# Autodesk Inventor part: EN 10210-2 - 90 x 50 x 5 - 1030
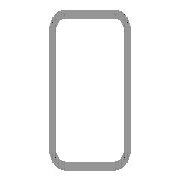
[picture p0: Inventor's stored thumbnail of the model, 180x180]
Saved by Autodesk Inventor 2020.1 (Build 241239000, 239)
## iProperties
Created: 2019-01
Part Number: EN 10210-2 - 90 x 50 x 5 - 1030
Material: Stahl, weich
Description: Rohrleitung
Document SubType Name: Modeling
Standard: DIN
Designer: lutzd
Standard Revision: 2006-07
Standards Organization: DIN
Language: de-DE
Size Designation: 90 x 50 x 5
Categories: <MemberInstance><Categories><Category DisplayName="Profile" InternalName="089c4875-fa83-4c05-b084-43b9cc11f5ed" Mnemonic="GRDR"><CategoryParameter DisplayName="
Stock Number: 90 x 50 x 5
Mass: 10294.3 g
Surface Area: 5160.42 cm^2
Volume: 1311.37 cm^3
Density: 7.85 g/cm^3
Appearance: Halbpoliert
IsCustomPart: 1
G_W: 50,000 mm
G_H: 90,000 mm
DocNumber: ADSK-014221
Folder: .
Dimensions: 50x90x1030 mm
Mass: 10,294 kg
+27136E20-D75B-4159-8830-D95EEF26A210+SCHNITTDETAIL1: Schnittwinkel 90,00 grd
+CEBB8236-4632-479D-8D11-BF2C99D5F906+SCHNITTDETAIL2: Schnittwinkel 90,00 grd
G_L: 1030,000 mm
_CCFamilyMember: 153
_CCFamilyDisplayName: DIN EN 10210-2 (USAS B17.1 rechteckig) - Rohrleitung — In Klammern angegebene Größen wurden aufgehoben
_FrameMemberDoc: Frame Member File
_Version: 15.0.0
_GetPNFromCC: 1
Title: Profil-Bauteil
Author: lutzd
Revision Number: -
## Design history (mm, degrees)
node "Startebene"
node "Endebene"
sketch "Skizze"
  geometry: L1 (-25, -37.5)-(-25, 37.5); L2 (-17.5, 45)-(17.5, 45); L3 (25, 37.5)-(25, -37.5); L4 (17.5, -45)-(-17.5, -45); L5 (-15, 40)-(15, 40); L6 (20, 35)-(20, -35); L7 (15, -40)-(-15, -40); L8 (-20, -35)-(-20, 35); L9 (0, 65.175)-(0, -65.175) reference; L10 (-37.175, 0)-(37.175, 0) reference; A1 r 7.5 centre (-17.5, -37.5) between (-25, -37.5) and (-17.5, -45); A2 r 7.5 centre (-17.5, 37.5) between (-17.5, 45) and (-25, 37.5); A3 r 7.5 centre (17.5, 37.5) between (25, 37.5) and (17.5, 45); A4 r 7.5 centre (17.5, -37.5) between (17.5, -45) and (25, -37.5); A5 r 5 centre (-15, -35) between (-20, -35) and (-15, -40); A6 r 5 centre (-15, 35) between (-15, 40) and (-20, 35); A7 r 5 centre (15, 35) between (20, 35) and (15, 40); A8 r 5 centre (15, -35) between (15, -40) and (20, -35)
  constraints: 16 end point, 16 point on circle, 16 tangent, 8 centre point, 6 equal radius, 4 parallel, 2 perpendicular, 2 other
  dimensions: "d7" = 7.5 radius of A1 (= G_IR); "d10" = 90 distance between parallel lines of L2 L4 (= G_H); "d11" = 50 distance between parallel lines of L1 L3 (= G_W); "d12" = 5 distance between parallel lines of L3 L6 (= G_T); "d15" = 45 distance between parallel lines of L2 L10 (= 0.5 x d10); "d16" = 25 distance between parallel lines of L9 L3 (= 0.5 x d11); "d19" = 5 radius of A5 (= G_T); "d20" = 5 distance between parallel lines of L4 L7 (= G_T)
extrude "Körper" new body sketch "Skizze" stored distance "d3" = 1030 (= G_L); taper "d4" = 0 deg
node "Driven Length"
  sketch "Sketch3"
    geometry: L1 (0, 0)-(10, 0) reference
    constraints: 2 end point, 1 horizontal
  workplane "Work Plane3"
  sketch "Sketch4"
    geometry: L1 (-2, 25)-(12, 25) reference; L2 (-2, 1055)-(12, 1055) reference
    dimensions: "d18" = 1030 distance between parallel lines of L1 L2 (derived)
workplane "Arbeitsebene4"
feature "Trennen1"
workplane "Arbeitsebene5"
feature "Trennen2"
body "Solid1"
other parameters: "G_W" = 50 [user parameter; used in 1 equation term], "G_H" = 90 [user parameter; used in 1 equation term], "G_T" = 5 [user parameter; used in 3 equation terms], "G_IR" = 7.5 [user parameter; used in 1 equation term], "G_L" = 1030 (= d18) [user parameter; used in 1 equation term], "G_OFFSET_START" = -25 [user parameter; used in 1 equation term], "d13" = 25 (= -G_OFFSET_START), "d14" = 1055 (= G_OFFSET_END + B_L), "B_L" = 1105 [user parameter; used in 1 equation term], "d17" = 90 deg
